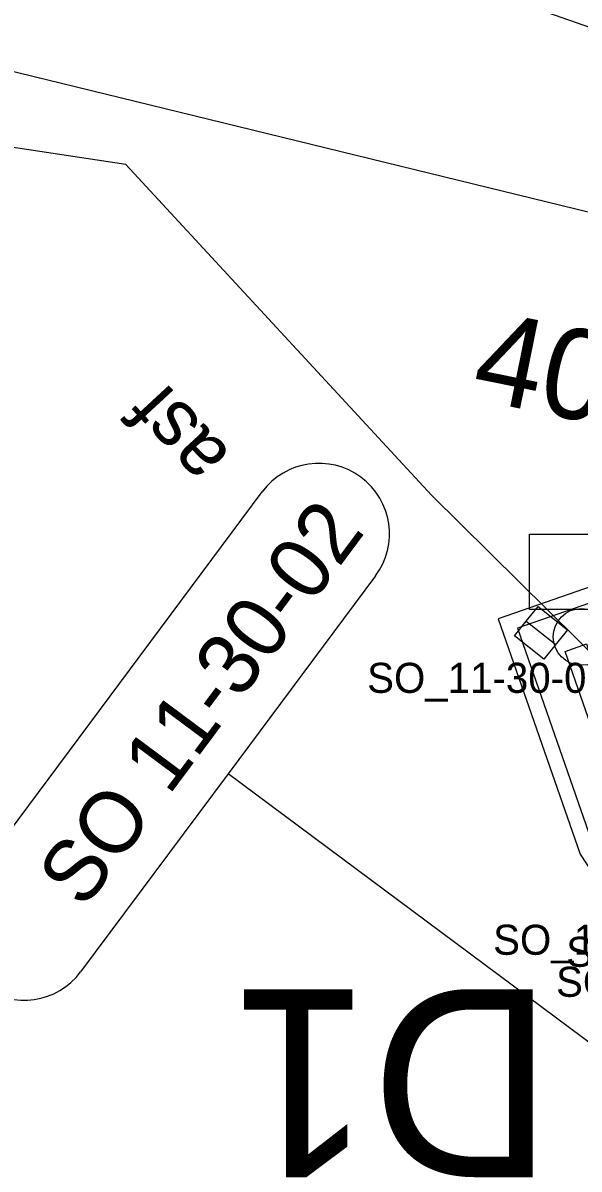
# Model space of a CAD drawing. Extents: x -728800 to -728100, y -1073200 to -1072700.
# Drawn here: x -728528.76 to -728521.37, y -1073056.81 to -1073041.57 of the extents above; entities that cross this region are included whole.
import ezdxf

# ---------------------------------------------------------------- set-up
doc = ezdxf.new("R2010")
doc.units = 0
for name, color, linetype in [('_NOR-návrh tenká', 7, 'Continuous'), ('_NOR-šraf_vozovka', 7, 'Continuous'), ('A1_OBVOD Spravy železnic', 7, 'Continuous'), ('A2_OBVOD STAVBY', 7, 'Continuous'), ('B3_body_popiska', 7, 'Continuous'), ('B4_Bodové pole', 7, 'Continuous'), ('B6_JŽM', 7, 'Continuous'), ('ZA_02_Dočasný_do_1_roku', 7, 'Continuous'), ('ZZZ_popisky', 7, 'Continuous')]:
    doc.layers.add(name, color=color, linetype=linetype)

msp = doc.modelspace()

# ---------------------------------------------------------------- linework, layer by layer
at = {"layer": '_NOR-návrh tenká'}
msp.add_lwpolyline([(-728520.701, -1073052.369), (-728521.551, -1073049.925), (-728521.267, -1073049.826)], dxfattribs=at)
at = {"layer": '_NOR-šraf_vozovka'}
for points in [[(-728521.551, -1073049.925), (-728521.267, -1073049.826), (-728520.417, -1073052.27)], [(-728520.701, -1073052.369), (-728521.551, -1073049.925)]]:
    msp.add_lwpolyline(points, dxfattribs=at)
at = {"layer": 'A1_OBVOD Spravy železnic'}
msp.add_lwpolyline([(-728582.13, -1073004.22), (-728564.68, -1073020.02), (-728543.86, -1073026.9), (-728510.71, -1073032.54), (-728510.22, -1073036.28), (-728509.415, -1073042.185), (-728509.9, -1073046.86), (-728541.12, -1073039.22), (-728572.55, -1073027.78)], dxfattribs=at)
at = {"layer": 'A2_OBVOD STAVBY'}
msp.add_lwpolyline([(-728517.209, -1073045.129), (-728517.596, -1073047.2), (-728520.569, -1073048.842), (-728522.442, -1073049.494), (-728521.354, -1073052.622), (-728520.331, -1073054.186), (-728521.735, -1073059.131)], dxfattribs=at)
at = {"layer": 'B4_Bodové pole'}
msp.add_lwpolyline([(-728665.963, -1072915.444), (-728594.709, -1073015.734), (-728502.086, -1073048.369), (-728347.458, -1073023.537)], dxfattribs=at)
msp.add_circle((-728521.333, -1073049.732), 0.378, dxfattribs=at)
at = {"layer": 'B6_JŽM'}
for points in [[(-728519.061, -1073052.066), (-728523.329, -1073047.846), (-728527.39, -1073043.448), (-728532.404, -1073042.69)], [(-728522.025, -1073048.368), (-728521.025, -1073048.368), (-728521.025, -1073049.368), (-728522.025, -1073049.368), (-728522.025, -1073048.368)], [(-728522.068, -1073049.523), (-728521.912, -1073049.328), (-728521.522, -1073049.64), (-728521.834, -1073050.03), (-728522.224, -1073049.718), (-728522.068, -1073049.523), (-728521.678, -1073049.835)]]:
    msp.add_lwpolyline(points, dxfattribs=at)
at = {"layer": 'ZA_02_Dočasný_do_1_roku'}
msp.add_lwpolyline([(-728515.203, -1073056.818), (-728511.189, -1073055.123), (-728508.595, -1073049.535), (-728508.492, -1073048.637), (-728517.382, -1073047.311), (-728520.487, -1073049.026), (-728522.187, -1073049.617), (-728521.173, -1073052.533), (-728520.113, -1073054.153), (-728521.586, -1073059.338)], dxfattribs=at)
at = {"layer": 'ZZZ_popisky'}
for points in [[(-728529.495, -1073053.067), (-728525.577, -1073047.802)], [(-728524.073, -1073048.922), (-728526.032, -1073051.554)], [(-728519.225, -1073056.62), (-728526.032, -1073051.554), (-728527.991, -1073054.187)]]:
    msp.add_lwpolyline(points, dxfattribs=at)
for centre, start, end in [((-728524.825, -1073048.362), 323.3447, 143.3447), ((-728528.743, -1073053.627), 143.3447, 323.3447)]:
    msp.add_arc(centre, 0.938, start, end, dxfattribs=at)

# ---------------------------------------------------------------- texts
at = {"layer": 'B3_body_popiska'}
for s, p in [('SO_11-30-01', (-728524.183, -1073050.477)), ('SO_11-30-01', (-728522.509, -1073053.96)), ('SO_11-30-01', (-728521.538, -1073054.12)), ('SO_11-30-02', (-728521.673, -1073054.519))]:
    msp.add_text(s, height=0.4, dxfattribs=at).set_placement(p)
at = {"layer": 'B4_Bodové pole'}
msp.add_text('4004', height=1.2, rotation=348.5433, dxfattribs=at).set_placement((-728522.827, -1073046.559))
at = {"layer": 'B6_JŽM'}
msp.add_text('asf', height=0.75, rotation=132.7186, dxfattribs=at).set_placement((-728525.981, -1073047.296))
at = {"layer": 'ZA_02_Dočasný_do_1_roku'}
msp.add_text('D1', height=2.5, rotation=180, dxfattribs=at).set_placement((-728521.71, -1073054.418))
at = {"layer": 'ZZZ_popisky'}
msp.add_text('SO 11-30-02', height=0.82031, rotation=53.3447, dxfattribs=at).set_placement((-728527.948, -1073053.37))

doc.saveas('drawing.dxf')
